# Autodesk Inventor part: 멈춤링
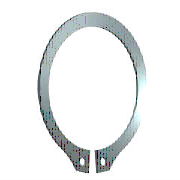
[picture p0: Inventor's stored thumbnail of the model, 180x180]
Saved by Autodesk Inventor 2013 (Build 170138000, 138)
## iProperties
IsCustomPart: 1
Company: 한국ATC센터
Created: 2014-10
Part Number: 멈춤링
Material: 강, 연강
Description: 리테이닝 링(C형)
Document SubType Name: Modeling
Standard: KS B 1336
Designer: 한국ATC센터
Standards Organization: KS
Language: ko-KR
Size Designation: 25 x 1.2
Categories: <MemberInstance><Categories><Category DisplayName="샤프트 부품" InternalName="7f7aeb1f-a693-4053-b835-cee3144e0d98" Mnemonic="SHFT"><Category DisplayName="써클립" Inter
Density: 7.86 g/cm^3
Mass: 2.3429 g
Surface Area: 7.2498 cm^2
Volume: 0.298079 cm^3
Author: KYOUNG IL JANG
Revision Number: 1
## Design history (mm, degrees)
sketch "스케치1"
  geometry: L1 (-6, 0)-(6, 0) reference; L2 (0, 20.189)-(0, -80.536) reference; L3 (-48.09, 0)-(48.09, 0) reference; L4 (-0.5, -24.44)-(-0.5, -28.74); L5 (-0.5, -6.54)-(-0.5, -13.29); L6 (-2.795, 3.1)-(3.672, 3.1); L7 (0.5, -6.54)-(0.5, -13.29); L8 (0.5, -24.44)-(0.5, -28.74); C1 r 1 at (-2, -26.606); C2 r 1 at (2, -26.606); A1 r 11.95 centre (0, -12.5) between (0.5, -24.44) and (-0.5, -24.44); A2 r 14.825 centre (0, -11.725) between (5.202, -25.608) and (-5.202, -25.608); A3 r 16.247 centre (0, -12.5) between (-2.281, -28.586) and (-0.5, -28.74); A4 r 2 centre (-2, -26.606) between (-3.952, -27.043) and (-2.281, -28.586); A5 r 2 centre (-5.903, -27.48) between (-3.952, -27.043) and (-5.202, -25.608); A6 r 2 centre (5.903, -27.48) between (5.202, -25.608) and (3.952, -27.043); A7 r 2 centre (2, -26.606) between (2.281, -28.586) and (3.952, -27.043); A8 r 16.247 centre (0, -12.5) between (0.5, -28.74) and (2.281, -28.586)
  constraints: 16 point on circle, 12 end point, 10 centre point, 9 symmetric about line, 5 point on line, 4 tangent, 3 coincident, 2 horizontal, 1 perpendicular, 1 vertical, 5 other
  dimensions: "d0" = 23.9 diameter of A1 (= ND); "d1" = 4.3 distance of L4.end L4.start (= SRB2); "d6" = 0.5 distance between parallel lines of L2 L5 (= 0.25 x SD5); "d7" = 3.1 distance between parallel lines of L6 L3 (= SRB1); "d8" = 0.775 distance of A1.centre A2.centre (= 0.25 x SRB1); "d9" = 2 radius of A4 (= SD5); "d10" = 2 radius of A5 (= SD5); "d11" = 1.5 distance from line of L4 A4.centre (= 0.75 x SD5); "d12" = 2 diameter of C1 (= SD5); "d13" = 2 diameter of C2 (= SD5); "d14" = 12.5 distance from line of A1.centre L1 (= 0.5 x WD)
extrude "본체" new body sketch "스케치1" distance "d2" = 1.2 (= SD); taper "d3" = 0 deg
workaxis "Work Axis1"
workplane "Work Plane1"
body "Solid1"
other parameters: "WD" = 25 (= WDMIN) [user parameter; used in 1 equation term], "SD" = 1.2 [user parameter; used in 1 equation term], "SRB1" = 3.1 [user parameter; used in 2 equation terms], "ND" = 23.9 [user parameter; used in 1 equation term], "SRB2" = 4.3 [user parameter; used in 1 equation term], "SD5" = 2 [user parameter; used in 6 equation terms], "d15" = 0, "d16" = 0, "d17" = 0, "d41" = 0, "d42" = 0, "WDMIN" = 25 [user parameter; used in 1 equation term], "SD3" = 23.2 [user parameter], "WDMAX" = 26 [user parameter]
